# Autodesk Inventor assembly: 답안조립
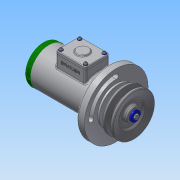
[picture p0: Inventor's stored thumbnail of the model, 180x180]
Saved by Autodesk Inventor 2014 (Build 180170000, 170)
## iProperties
Created: 2017-05
Part Number: 답안조립
Document SubType Name: Assembly
Designer: user
Author: user
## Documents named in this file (20)
- C:\Users\user\Desktop\470508V1013\답안조립.iam
- C:\Users\user\Desktop\470508V1013\1-본체.ipt
- C:\Users\user\Desktop\470508V1013\사이드 커버.ipt
- 사이드 커버.ipt
- C:\Users\user\Desktop\470508V1013\탑 커버.ipt
- C:\Users\user\Desktop\470508V1013\축.ipt
- C:\Users\user\Desktop\470508V1013\너트 M10.ipt
- C:\Users\user\Desktop\470508V1013\와셔 10x21.ipt
- C:\Users\user\Desktop\470508V1013\부시1.ipt
- C:\Users\user\Desktop\470508V1013\멈춤링 15 x 1.ipt
- C:\Users\user\Desktop\470508V1013\베어링 15 x 35 x 11.ipt
- C:\Users\user\Desktop\470508V1013\멈춤링 35x1.6.ipt
- C:\Users\user\Desktop\470508V1013\부시2.ipt
- C:\Users\user\Desktop\470508V1013\오일 실 15 25 7.ipt
- C:\Users\user\Desktop\470508V1013\키 4 x 4 x 18.ipt
- C:\Users\user\Desktop\470508V1013\와셔 4x16.ipt
- C:\Users\user\Desktop\470508V1013\볼트 M4 x 10.ipt
- C:\Users\user\Desktop\470508V1013\V-벨트풀리.ipt
- C:\Users\user\Desktop\470508V1013\와셔 3x6.ipt
- C:\Users\user\Desktop\470508V1013\십자볼트 M3 x 10.ipt
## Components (3 placed, 3 different names)
1. 1-본체:1 — Mate:1, Mate:2, Mate:3, Mate:4, Mate:5, Mate:6, Mate:26, Mate:34
2. ISO 4017 M4 x 10:1 — Insert:1
3. V-벨트풀리:1 — Mate:30, Angle:1, Mate:31
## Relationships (12: Mate 10, Angle 1, Insert 1)
- Mate:1: 1-본체:1
- Mate:2: 1-본체:1
- Mate:3: 1-본체:1
- Mate:4: 1-본체:1
- Mate:5: 1-본체:1
- Mate:6: 1-본체:1
- Mate:26: 1-본체:1
- Mate:30: V-벨트풀리:1
- Angle:1: V-벨트풀리:1
- Mate:31: V-벨트풀리:1
- Insert:1: ISO 4017 M4 x 10:1
- Mate:34: 1-본체:1
